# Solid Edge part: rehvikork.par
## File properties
Author: KULL
Template: Iso Metric Part.par
Last saved by: KULL
Revision: 4
Application: Solid Edge
Accuracy: 0,990
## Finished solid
Body 1: solid body, 93 faces, 217 edges, 128 vertices.
  Faces by surface: blend 40, spline 40, sphere 6, torus 3, cylinder 2, cone 1, plane 1
  Edges by curve: intersection 128, circle 49, line 40
Bounding box of the edges (mm; curved faces can reach further): 4.951 x 16.000 x 16.000, from (-4, -8, -8) to (0.951, 8, 8).
Cylindrical faces by radius (mm): R7 x1, R8 x1
Conical faces (half-angle, radius in mm at the cone's reference point): 11.8765 deg R7 x1
Toroidal faces (ring radius, tube radius in mm): R7.0618 r0.08 x1, R7.6 r0.4 x1, R7.92 r0.08 x1
Spherical faces by radius (mm): R33.0132 x1, R33.5132 x2, R34.0132 x3
Planar faces by outward normal: -x 1
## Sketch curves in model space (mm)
circle centre (4.1723, 0, 0) radius 7
arc centre (4.1723, -5.154, -2.9757) radius 0.4 from (4.1723, -5.5537, -2.9929) through (4.1723, -5.5004, -3.1757) to (4.1723, -5.3688, -3.3131)
arc centre (4.1723, 0, 5.1235) radius 10 from (4.1723, 5.3688, -3.3131) through (4.1723, 0, -4.8765) to (4.1723, -5.3688, -3.3131)
arc centre (4.1723, 5.154, -2.9757) radius 0.4 from (4.1723, 5.3688, -3.3131) through (4.1723, 5.5004, -3.1757) to (4.1723, 5.5537, -2.9929)
arc centre (4.1723, -4.437, -2.5617) radius 10 from (4.1723, 0.1849, 6.3061) through (4.1723, 4.2232, 2.4383) to (4.1723, 5.5537, -2.9929)
arc centre (4.1723, 0, 5.9514) radius 0.4 from (4.1723, 0.1849, 6.3061) through (4.1723, 0, 6.3514) to (4.1723, -0.1849, 6.3061)
arc centre (4.1723, 4.437, -2.5617) radius 10 from (4.1723, -0.1849, 6.3061) through (4.1723, -4.2232, 2.4383) to (4.1723, -5.5537, -2.9929)
arc centre (4.1723, -0.6763, 0.7482) radius 0.2 from (4.1723, -0.6763, 0.5482) through (4.1723, -0.8218, 0.6109) to (4.1723, -0.8763, 0.7482)
line (4.1723, -0.8763, 0.7482) -> (4.1723, -0.8763, 2.26)
arc centre (4.1723, -1.0763, 2.26) radius 0.2 from (4.1723, -0.8763, 2.26) through (4.1723, -0.939, 2.4055) to (4.1723, -1.0763, 2.46)
line (4.1723, -1.0763, 2.46) -> (4.1723, -1.901, 2.46)
arc centre (4.1723, -1.901, 2.26) radius 0.2 from (4.1723, -1.901, 2.46) through (4.1723, -2.0465, 2.3973) to (4.1723, -2.101, 2.26)
line (4.1723, -2.101, 2.26) -> (4.1723, -2.101, 0)
line (4.1723, -2.101, -2.26) -> (4.1723, -2.101, 0)
arc centre (4.1723, -1.901, -2.26) radius 0.2 from (4.1723, -1.901, -2.46) through (4.1723, -2.0465, -2.3973) to (4.1723, -2.101, -2.26)
line (4.1723, -1.0763, -2.46) -> (4.1723, -1.901, -2.46)
arc centre (4.1723, -1.0763, -2.26) radius 0.2 from (4.1723, -0.8763, -2.26) through (4.1723, -0.939, -2.4055) to (4.1723, -1.0763, -2.46)
line (4.1723, -0.8763, -0.7482) -> (4.1723, -0.8763, -2.26)
arc centre (4.1723, -0.6763, -0.7482) radius 0.2 from (4.1723, -0.6763, -0.5482) through (4.1723, -0.8218, -0.6109) to (4.1723, -0.8763, -0.7482)
line (4.1723, 0, -0.5482) -> (4.1723, -0.6763, -0.5482)
line (4.1723, 0, -0.5482) -> (4.1723, 0.6763, -0.5482)
arc centre (4.1723, 0.6763, -0.7482) radius 0.2 from (4.1723, 0.6763, -0.5482) through (4.1723, 0.8218, -0.6109) to (4.1723, 0.8763, -0.7482)
line (4.1723, 0.8763, -0.7482) -> (4.1723, 0.8763, -2.26)
arc centre (4.1723, 1.0763, -2.26) radius 0.2 from (4.1723, 0.8763, -2.26) through (4.1723, 0.939, -2.4055) to (4.1723, 1.0763, -2.46)
line (4.1723, 1.0763, -2.46) -> (4.1723, 1.901, -2.46)
arc centre (4.1723, 1.901, -2.26) radius 0.2 from (4.1723, 1.901, -2.46) through (4.1723, 2.0465, -2.3973) to (4.1723, 2.101, -2.26)
line (4.1723, 2.101, -2.26) -> (4.1723, 2.101, 0)
line (4.1723, 2.101, 2.26) -> (4.1723, 2.101, 0)
arc centre (4.1723, 1.901, 2.26) radius 0.2 from (4.1723, 1.901, 2.46) through (4.1723, 2.0465, 2.3973) to (4.1723, 2.101, 2.26)
line (4.1723, 1.0763, 2.46) -> (4.1723, 1.901, 2.46)
arc centre (4.1723, 1.0763, 2.26) radius 0.2 from (4.1723, 0.8763, 2.26) through (4.1723, 0.939, 2.4055) to (4.1723, 1.0763, 2.46)
line (4.1723, 0.8763, 0.7482) -> (4.1723, 0.8763, 2.26)
arc centre (4.1723, 0.6763, 0.7482) radius 0.2 from (4.1723, 0.6763, 0.5482) through (4.1723, 0.8218, 0.6109) to (4.1723, 0.8763, 0.7482)
line (4.1723, 0, 0.5482) -> (4.1723, 0.6763, 0.5482)
line (4.1723, 0, 0.5482) -> (4.1723, -0.6763, 0.5482)
arc centre (4.1723, 4.1615, -2.4026) radius 0.4 from (4.1723, 4.355, -2.7527) through (4.1723, 4.5079, -2.6026) to (4.1723, 4.5614, -2.3952)
arc centre (4.1723, 0, 5.1235) radius 9 from (4.1723, 4.355, -2.7527) through (4.1723, 0, -3.8765) to (4.1723, -4.355, -2.7527)
arc centre (4.1723, -4.1615, -2.4026) radius 0.4 from (4.1723, -4.5614, -2.3952) through (4.1723, -4.5079, -2.6026) to (4.1723, -4.355, -2.7527)
arc centre (4.1723, 4.437, -2.5617) radius 9 from (4.1723, -4.5614, -2.3952) through (4.1723, -3.3572, 1.9383) to (4.1723, -0.2064, 5.1479)
arc centre (4.1723, 0, 4.8053) radius 0.4 from (4.1723, 0.2064, 5.1479) through (4.1723, 0, 5.2053) to (4.1723, -0.2064, 5.1479)
arc centre (4.1723, -4.437, -2.5617) radius 9 from (4.1723, 0.2064, 5.1479) through (4.1723, 3.3572, 1.9383) to (4.1723, 4.5614, -2.3952)
circle centre (0, 0, 0) radius 8
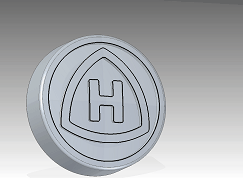
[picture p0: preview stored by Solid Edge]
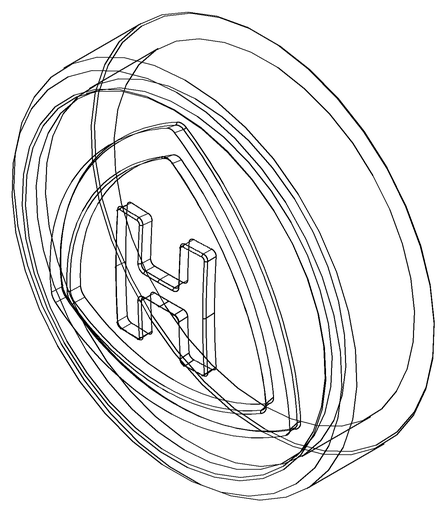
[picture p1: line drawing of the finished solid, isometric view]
